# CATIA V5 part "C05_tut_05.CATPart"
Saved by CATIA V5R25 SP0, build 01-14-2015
Part number: Part1
Bounding box of the stored display mesh (mm): x -12 to 12, y 0 to 251, z -11.999 to 11.999
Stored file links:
  E:\ashutosh\Academics\Catia\CATIA V5-6R2013_partfiles\Tutorials_ver_2\C05_tut_05.CATPart
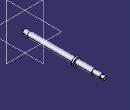
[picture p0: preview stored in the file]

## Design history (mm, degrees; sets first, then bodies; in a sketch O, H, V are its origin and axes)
Body1 (main body)
  Sketch1 on zx-plane, origin (0, 0, 0), H (-1, 0, 0), V (0, 0, 1)
    circle A1 centre (0, 0) radius 12
    circle A2 centre (0, 0) radius 8
    circle A3 centre (0, 0) radius 7
    circle A4 centre (0, 0) radius 6.5
    circle A5 centre (0, 0) radius 5
    radius A5 = 5
    radius A4 = 6.5
    radius A3 = 7
    radius A2 = 8
    radius A1 = 12
  MultiPad1: profile Sketch1, domains (length 251; length 240; length 16; length 216 / length -16; length 164 / length -158)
